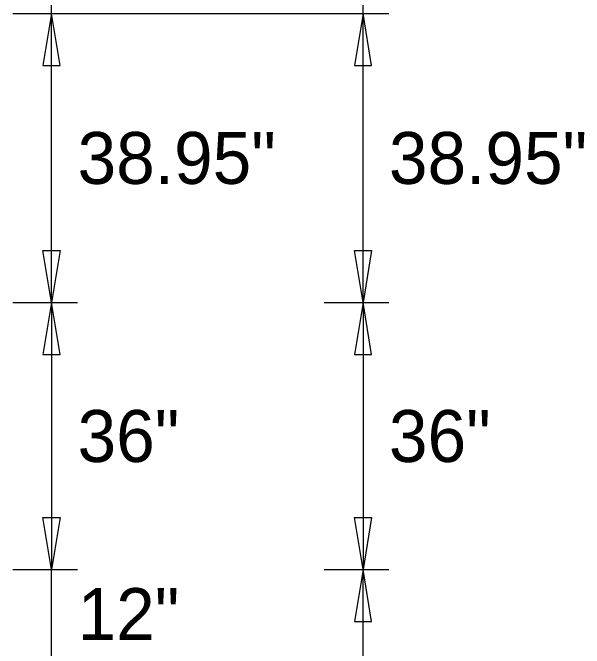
# Model space of a CAD drawing. Extents: x 2149961 to 2150220, y 145114 to 145240.
# Drawn here: x 2150106.51 to 2150112.93, y 145153.67 to 145160.81 of the extents above; entities that cross this region are included whole.
import ezdxf

# ---------------------------------------------------------------- set-up
doc = ezdxf.new("R2010")
doc.units = 0
doc.layers.add('GSDIMS', color=7, linetype='Continuous')

msp = doc.modelspace()

# ---------------------------------------------------------------- linework, layer by layer
at = {"layer": 'GSDIMS'}
for p, q in [((2150106.9455, 145160.7996), (2150106.9455, 145161.5874)), ((2150110.4455, 145160.7996), (2150110.4455, 145161.5874)), ((2150106.5079, 145160.7997), (2150107.237, 145160.7997)), ((2150106.5079, 145160.7997), (2150110.0079, 145160.7997)), ((2150106.508, 145160.7996), (2150107.2371, 145160.7996)), ((2150106.508, 145160.7996), (2150110.008, 145160.7996)), ((2150106.9454, 145157.554), (2150106.9454, 145160.7997)), ((2150110.0079, 145160.7997), (2150110.737, 145160.7997)), ((2150110.008, 145160.7996), (2150110.7371, 145160.7996)), ((2150110.4454, 145157.554), (2150110.4454, 145160.7997)), ((2150106.5079, 145157.554), (2150107.237, 145157.554)), ((2150106.5079, 145157.554), (2150107.237, 145157.554)), ((2150106.9454, 145157.554), (2150106.9454, 145154.5539)), ((2150110.0079, 145157.554), (2150110.737, 145157.554)), ((2150110.0079, 145157.554), (2150110.737, 145157.554)), ((2150110.4454, 145157.554), (2150110.4454, 145154.5539)), ((2150106.5079, 145154.5539), (2150107.237, 145154.5539)), ((2150106.5079, 145154.5539), (2150107.237, 145154.5539)), ((2150106.9454, 145153.554), (2150106.9454, 145154.5539)), ((2150110.0079, 145154.5539), (2150110.737, 145154.5539)), ((2150110.0079, 145154.5539), (2150110.737, 145154.5539)), ((2150110.4454, 145146.2997), (2150110.4454, 145154.5539))]:
    msp.add_line(p, q, dxfattribs=at)
for points in [[(2150106.9454, 145160.7997), (2150106.8481, 145160.2164), (2150107.0426, 145160.2164)], [(2150110.4454, 145160.7997), (2150110.3481, 145160.2164), (2150110.5426, 145160.2164)], [(2150106.9454, 145157.554), (2150106.8481, 145158.1373), (2150107.0426, 145158.1373)], [(2150110.4454, 145157.554), (2150110.3481, 145158.1373), (2150110.5426, 145158.1373)], [(2150106.9454, 145157.554), (2150106.8481, 145156.9707), (2150107.0426, 145156.9707)], [(2150110.4454, 145157.554), (2150110.3481, 145156.9707), (2150110.5426, 145156.9707)], [(2150106.9454, 145154.5539), (2150106.8481, 145155.1372), (2150107.0426, 145155.1372)], [(2150110.4454, 145154.5539), (2150110.3481, 145155.1372), (2150110.5426, 145155.1372)], [(2150110.4454, 145154.5539), (2150110.3481, 145153.9706), (2150110.5426, 145153.9706)]]:
    msp.add_lwpolyline(points, close=True, dxfattribs=at)

# ---------------------------------------------------------------- texts
for s, p in [('38.95"', (2150107.2371, 145158.8852)), ('38.95"', (2150110.7371, 145158.8852)), ('36"', (2150107.2371, 145155.7623)), ('36"', (2150110.7371, 145155.7623)), ('12"', (2150107.2371, 145153.7623))]:
    msp.add_text(s, height=0.58333, dxfattribs=at).set_placement(p)

doc.saveas('drawing.dxf')
